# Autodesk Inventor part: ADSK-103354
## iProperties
Created: 2000-08
Part Number: ADSK-103354
Description: Helical Spring Lock Washer
Document SubType Name: Modeling
Standard: ASME B18.21.1 - 1/2 Regular. Carbon Steel
Designer: gao
Density: 1 g/cm^3
Control State: 0
Master: False
Checked Out: False
Shininess: 0.0
Density: 0.0
Volumn: 0.0
Area: 0.0
PropertySet Name: Model Information
Author: gao
